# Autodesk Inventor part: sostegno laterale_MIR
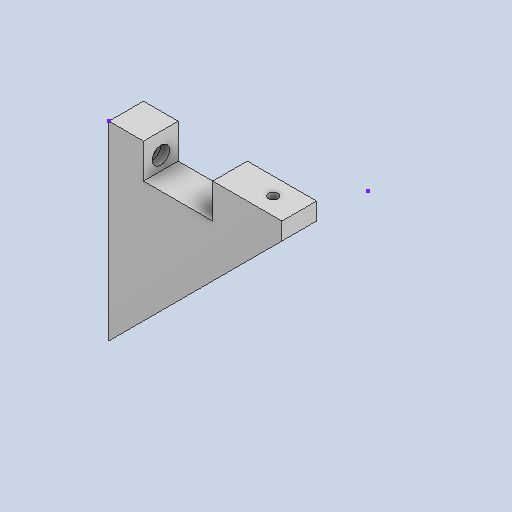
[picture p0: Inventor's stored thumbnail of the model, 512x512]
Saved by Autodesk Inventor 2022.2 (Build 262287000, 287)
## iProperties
Created: 2024-10
Part Number: sostegno laterale_MIR
Material: Alluminio 6061
Document SubType Name: Modeling
Designer: 18907419
Density: 2.7 g/cm^3
Appearance: Default
Author: 18907419
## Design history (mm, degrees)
node "Geometria corretta1"
  sketch "Schizzo6"
feature "Solido1"
node "Schizzo3"
node "Solido2"
